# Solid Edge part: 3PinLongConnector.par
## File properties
Author: conerly
Template: Ansi Part.par
Last saved by: jccrumbl
Revision: 24
Application: Solid Edge
Density: 0.0979772159 lbm/in^3
Accuracy: 0.990
Material: Aluminum, 1060
Face Style: Aluminum
Fill Style: ANSI38(Aluminum)
Virtual Style: Polished aluminum
Coef. of Thermal Exp: 2.3e-05
Thermal Conductivity: 221.0
Specific Heat: 920.0
Modulus of Elasticity: 68947570000.0
Poisson's Ratio: 0.33
Yield Stress: 27579028.0
Ultimate Stress: 68947570.0
Elongation: 0.0
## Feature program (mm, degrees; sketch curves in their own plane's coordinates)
sketch for "unnamed Protrusion 1" plane through (10.8687, 10.8687, 0) normal (0, 0, 1) x-axis (1, 0, 0)
  line (-10.8687, -10.8687) -> (-4.5187, -10.8687)
  line (-4.5187, -10.8687) -> (-4.5187, 1.8313)
  line (-4.5187, 1.8313) -> (1.8313, 1.8313)
  line (1.8313, 1.8313) -> (1.8313, 14.5313)
  line (1.8313, 14.5313) -> (8.1813, 14.5313)
  line (8.1813, 14.5313) -> (8.1813, 27.2313)
  line (8.1813, 27.2313) -> (-10.8687, 27.2313)
  line (-10.8687, 27.2313) -> (-10.8687, -10.8687)
  dimension (linear) = 4.5187
  dimension (linear) = 1.8313
  dimension (linear) = 8.1813
  dimension (linear) = 10.8687
extrude "unnamed Protrusion 1" add finite 6.35 symmetric
sketch for "ExtrudedCutout_1" plane through (3.175, 0, 0) normal (0, -1, 0) x-axis (1, 0, 0)
  circle centre (0, 0) radius 1.27
extrude "ExtrudedCutout_1" cut finite 1.524 along -normal
sketch for "ExtrudedCutout_2" plane through (9.3638, 12.7, -0.0457) normal (0, -1, 0) x-axis (1, 0, 0)
  circle centre (0.1612, 0.0457) radius 1.27
extrude "ExtrudedCutout_2" cut finite 1.524 along -normal
sketch for "ExtrudedCutout_3" plane through (15.8086, 25.4, -0.1934) normal (0, -1, 0) x-axis (1, 0, 0)
  circle centre (0.0664, 0.1934) radius 1.27
extrude "ExtrudedCutout_3" cut finite 1.524 along -normal
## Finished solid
Body 1: solid body, 16 faces, 30 edges, 16 vertices.
  Faces by surface: plane 13, cylinder 3
  Edges by curve: line 24, circle 6
Bounding box of the edges (mm): 19.050 x 38.100 x 6.350, from (0, 0, -3.175) to (19.05, 38.1, 3.175).
Cylindrical faces by radius (mm): R1.27 x3
Planar faces by outward normal: +x 3, +y 1, +z 1, -x 1, -y 6, -z 1
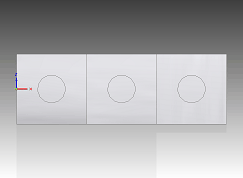
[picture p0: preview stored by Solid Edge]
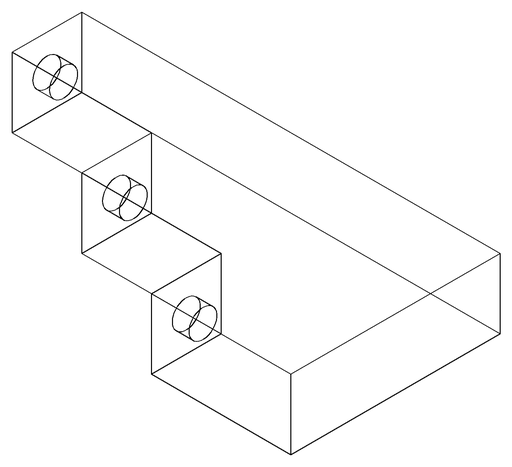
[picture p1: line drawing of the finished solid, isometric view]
